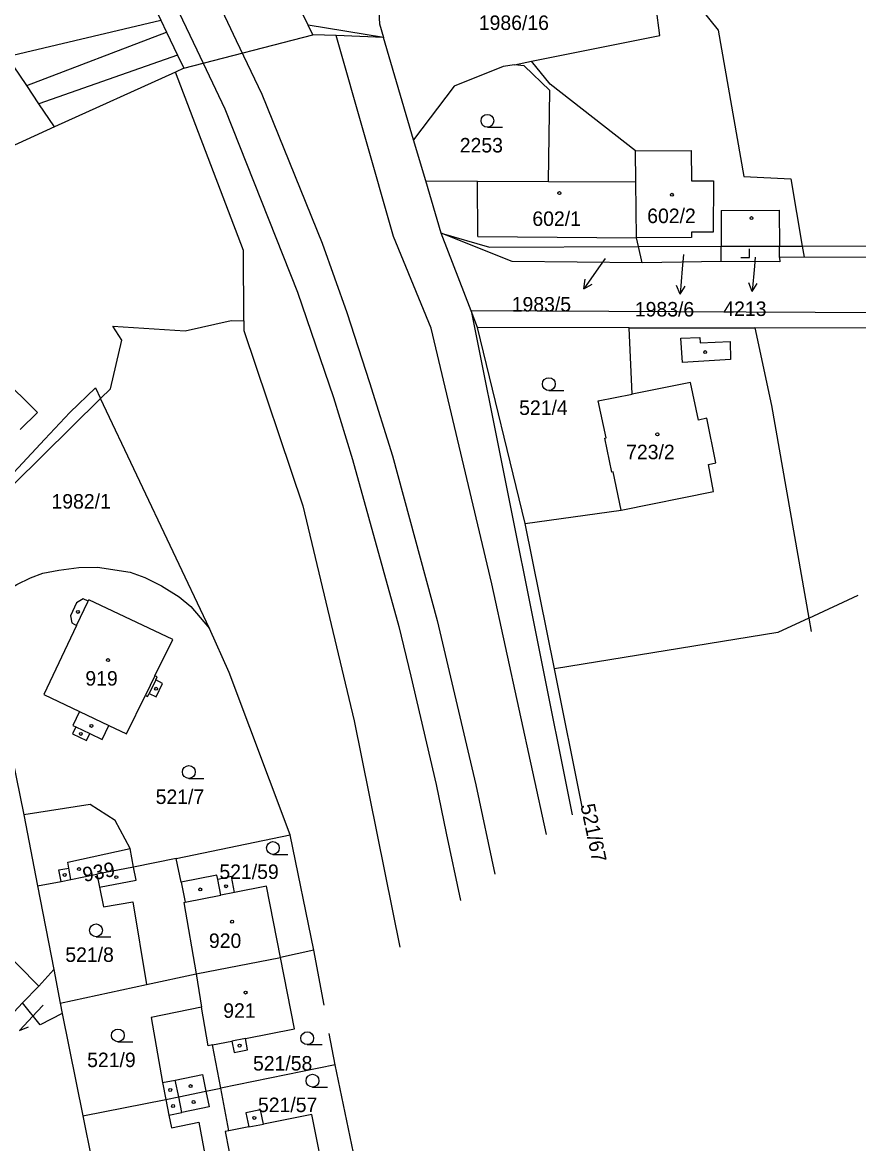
# Model space of a CAD drawing. Extents: x -679220 to -673243, y -1075091 to -1066557.
# Drawn here: x -675840.9 to -675742.9, y -1071652.9 to -1071521.5 of the extents above; entities that cross this region are included whole.
import ezdxf

# ---------------------------------------------------------------- set-up
doc = ezdxf.new("R2010")
doc.units = 0
for name, color, linetype in [('Hranice parcel', 7, 'Continuous'), ('Parcelní čísla', 7, 'Continuous'), ('Pop  PČ popisy', 7, 'Continuous'), ('Poz předměty', 7, 'Continuous'), ('Vnitřní kresba', 7, 'Continuous'), ('Značky budov', 7, 'Continuous'), ('Značky kultur', 7, 'Continuous')]:
    doc.layers.add(name, color=color, linetype=linetype)

msp = doc.modelspace()

# ---------------------------------------------------------------- linework, layer by layer
at = {"layer": 'Hranice parcel'}
for p, q in [((-675762.66, -1071518.33), (-675759.37, -1071522.39)), ((-675798.6, -1071523.24), (-675804.16, -1071523.03)), ((-675795.08, -1071535.25), (-675798.6, -1071523.24)), ((-675783.25, -1071526.44), (-675781.27, -1071526.04)), ((-675779.07, -1071528.74), (-675781.27, -1071526.04)), ((-675822.98, -1071527.31), (-675837.15, -1071533.74)), ((-675769.07, -1071536.52), (-675779.07, -1071528.74)), ((-675793.66, -1071540.05), (-675795.08, -1071535.25)), ((-675791.86, -1071546.18), (-675793.66, -1071540.05)), ((-675750.86, -1071539.81), (-675749.53, -1071547.7)), ((-675788.35, -1071555.28), (-675791.86, -1071546.18)), ((-675783.51, -1071549.52), (-675791.86, -1071546.18)), ((-675768.73, -1071547.76), (-675759.03, -1071547.73)), ((-675768.3, -1071549.66), (-675768.73, -1071547.76)), ((-675759.02, -1071549.52), (-675759.03, -1071547.73)), ((-675749.53, -1071547.7), (-675749.31, -1071549.02)), ((-675768.3, -1071549.66), (-675783.51, -1071549.52)), ((-675759.02, -1071549.52), (-675768.3, -1071549.66)), ((-675719.35, -1071549.05), (-675749.31, -1071549.02)), ((-675718.61, -1071555.66), (-675788.35, -1071555.28)), ((-675787.58, -1071557.26), (-675788.35, -1071555.28)), ((-675769.8, -1071557.28), (-675787.58, -1071557.26)), ((-675781.99, -1071580.21), (-675787.58, -1071557.26)), ((-675769.8, -1071557.28), (-675755.1, -1071557.3)), ((-675718.42, -1071557.34), (-675755.1, -1071557.3)), ((-675818.99, -1071592.52), (-675831.77, -1071565.57)), ((-675778.56, -1071597.27), (-675781.99, -1071580.21)), ((-675845.69, -1071590.25), (-675840.78, -1071614.39)), ((-675775.31, -1071613.45), (-675778.56, -1071597.27)), ((-675840.78, -1071614.39), (-675839.16, -1071622.71)), ((-675822.9, -1071619.49), (-675809.53, -1071616.74)), ((-675806.79, -1071630.23), (-675809.53, -1071616.74)), ((-675822.9, -1071619.49), (-675827.9, -1071620.52)), ((-675827.9, -1071620.52), (-675832.19, -1071621.34)), ((-675839.16, -1071622.71), (-675837.26, -1071632.53)), ((-675848.96, -1071624.39), (-675839.01, -1071634.47)), ((-675820.58, -1071633.03), (-675810.68, -1071631.09)), ((-675806.79, -1071630.23), (-675810.68, -1071631.09)), ((-675805.58, -1071636.68), (-675806.79, -1071630.23)), ((-675839.01, -1071634.47), (-675837.26, -1071632.53)), ((-675837.26, -1071632.53), (-675836.49, -1071636.46)), ((-675826.37, -1071634.28), (-675820.58, -1071633.03)), ((-675840.91, -1071636.43), (-675839.01, -1071634.47)), ((-675836.49, -1071636.46), (-675826.37, -1071634.28)), ((-675840.91, -1071636.43), (-675848.4, -1071644.43)), ((-675836.49, -1071636.46), (-675836.25, -1071637.68)), ((-675836.25, -1071637.68), (-675833.84, -1071649.66)), ((-675804.27, -1071643.7), (-675804.96, -1071640.02)), ((-675804.27, -1071643.7), (-675817.68, -1071646.43)), ((-675801.46, -1071657.17), (-675804.27, -1071643.7)), ((-675833.84, -1071649.66), (-675824.13, -1071647.74)), ((-675833.84, -1071649.66), (-675832.79, -1071654.92))]:
    msp.add_line(p, q, dxfattribs=at)
for points in [[(-675836.69, -1071505.46), (-675832.38, -1071505.2), (-675831.88, -1071506.24), (-675829.96, -1071510.26), (-675824.71, -1071521.21), (-675824.03, -1071522.63), (-675822.74, -1071525.31), (-675822, -1071526.86), (-675822.98, -1071527.31)], [(-675837.15, -1071533.74), (-675838.99, -1071531.01), (-675840.42, -1071528.88), (-675842.72, -1071525.48), (-675850.05, -1071514.58), (-675853.19, -1071509.92), (-675855.42, -1071506.6)], [(-675799.42, -1071515.63), (-675799.23, -1071518.87), (-675799.06, -1071521.66), (-675798.6, -1071523.24)], [(-675804.16, -1071523.03), (-675806.88, -1071522.93), (-675807.43, -1071521.79), (-675808.59, -1071519.4), (-675809.31, -1071517.91)], [(-675781.27, -1071526.04), (-675766.22, -1071523), (-675766.64, -1071519.74), (-675762.66, -1071518.33)], [(-675759.37, -1071522.39), (-675756.39, -1071539.53), (-675750.86, -1071539.81)], [(-675779.51, -1071616.68), (-675785.92, -1071587.32), (-675793.01, -1071557.34), (-675797.45, -1071546.6), (-675804.16, -1071523.03)], [(-675814.99, -1071556.47), (-675815.03, -1071548.22), (-675822.98, -1071527.31)], [(-675783.25, -1071526.44), (-675784.6, -1071526.66), (-675790.31, -1071528.97), (-675795.08, -1071535.25)], [(-675793.66, -1071540.05), (-675787.59, -1071540.08), (-675779.29, -1071540.12), (-675779.13, -1071529.46), (-675782.14, -1071526.56), (-675783.25, -1071526.44)], [(-675837.15, -1071533.74), (-675848.11, -1071538.72), (-675877.36, -1071543.69), (-675912.93, -1071549.73), (-675950.9, -1071556.66), (-675972.74, -1071561.14), (-676014.26, -1071571.02)], [(-675768.73, -1071547.76), (-675768.97, -1071546.72), (-675769.04, -1071540.18), (-675769.07, -1071536.52)], [(-675791.86, -1071546.18), (-675786.19, -1071547.82), (-675768.73, -1071547.76)], [(-675759.03, -1071547.73), (-675752.2, -1071547.71), (-675749.53, -1071547.7)], [(-675749.53, -1071547.7), (-675689.36, -1071547.5)], [(-675749.31, -1071549.02), (-675752.18, -1071549.03), (-675752.17, -1071549.55), (-675759.02, -1071549.52)], [(-675788.35, -1071555.28), (-675776.51, -1071614.37)], [(-675831.77, -1071565.57), (-675830.61, -1071564.43), (-675829.28, -1071558.72), (-675830.34, -1071557.08), (-675821.87, -1071557.66), (-675816.45, -1071556.43), (-675814.99, -1071556.47)], [(-675814.99, -1071556.47), (-675814.98, -1071557.6), (-675808.08, -1071578.16), (-675802.06, -1071603.35), (-675796.71, -1071629.88)], [(-675781.99, -1071580.21), (-675770.74, -1071578.68), (-675771.69, -1071574.18), (-675771.84, -1071574.21), (-675772.68, -1071570.22), (-675772.53, -1071570.19), (-675773.45, -1071565.86), (-675769.47, -1071565.06), (-675769.8, -1071557.28)], [(-675755.1, -1071557.3), (-675753.14, -1071566.4), (-675748.76, -1071591.32)], [(-675845.34, -1071564.8), (-675843.47, -1071562.95), (-675839.16, -1071567.22), (-675841.2, -1071569.22)], [(-675846.21, -1071576.54), (-675845.1, -1071577.61), (-675838.31, -1071570.35), (-675835.37, -1071567.23), (-675832.35, -1071564.34), (-675831.77, -1071565.57)], [(-675831.77, -1071565.57), (-675862.32, -1071595.73), (-675894.88, -1071628.17), (-675911.82, -1071645.32), (-675911.96, -1071645.47)], [(-675845.69, -1071590.25), (-675844.52, -1071589.23), (-675843.28, -1071588.35), (-675841.6, -1071587.37), (-675839.97, -1071586.6), (-675838.55, -1071586.06), (-675836.65, -1071585.68), (-675834.32, -1071585.37), (-675832.14, -1071585.35), (-675828.3, -1071585.95), (-675826.58, -1071586.56), (-675824.62, -1071587.52), (-675822.57, -1071588.81), (-675821.2, -1071589.94), (-675818.99, -1071592.52)], [(-675833.04, -1071604.85), (-675831.58, -1071605.55), (-675830.8, -1071603.9), (-675828.74, -1071604.89), (-675826.52, -1071600.37), (-675826.25, -1071600.5), (-675826.07, -1071600.14), (-675825.26, -1071600.54), (-675824.49, -1071598.97), (-675825.3, -1071598.57), (-675825.12, -1071598.21), (-675825.39, -1071598.08), (-675823.29, -1071593.82), (-675833.15, -1071589.18), (-675833.21, -1071589.32), (-675833.8, -1071589.04), (-675834.57, -1071589.51), (-675835.3, -1071591.04), (-675835.15, -1071591.89), (-675834.57, -1071592.17), (-675838.41, -1071600.27), (-675834.22, -1071602.27), (-675835, -1071603.91), (-675834.66, -1071604.07), (-675835.06, -1071604.89), (-675833.43, -1071605.67), (-675833.04, -1071604.85)], [(-675748.76, -1071591.32), (-675742.96, -1071588.63)], [(-675748.76, -1071591.32), (-675752.38, -1071593), (-675778.56, -1071597.27)], [(-675748.76, -1071591.32), (-675748.49, -1071592.87)], [(-675809.53, -1071616.74), (-675816.7, -1071597.7), (-675818.99, -1071592.52)], [(-675827.9, -1071620.52), (-675828.31, -1071618.32), (-675830.05, -1071615.03), (-675832.98, -1071613.18), (-675840.78, -1071614.39)], [(-675810.68, -1071631.09), (-675812.33, -1071622.75), (-675816.06, -1071623.49), (-675816.43, -1071621.63), (-675818.03, -1071621.95), (-675818.13, -1071621.46), (-675822.32, -1071622.29), (-675822.9, -1071619.49)], [(-675839.16, -1071622.71), (-675836.39, -1071622.18), (-675835.26, -1071621.96), (-675832.19, -1071621.34)], [(-675832.19, -1071621.34), (-675831.88, -1071622.86), (-675831.42, -1071625.17), (-675827.98, -1071624.59), (-675826.37, -1071634.28)], [(-675817.68, -1071646.43), (-675818.66, -1071641.36), (-675816.38, -1071640.91), (-675816.12, -1071642.23), (-675814.53, -1071641.92), (-675814.79, -1071640.6), (-675809.02, -1071639.48), (-675810.68, -1071631.09)], [(-675820.58, -1071633.03), (-675819.92, -1071636.93), (-675825.85, -1071638.16), (-675824.49, -1071645.78), (-675824.13, -1071647.74)], [(-675836.25, -1071637.68), (-675838.84, -1071639), (-675840.91, -1071636.43)], [(-675824.13, -1071647.74), (-675822.61, -1071647.43), (-675819.42, -1071646.78), (-675817.68, -1071646.43)], [(-675805.33, -1071657.94), (-675807.01, -1071649.5), (-675812.69, -1071650.63), (-675813.02, -1071648.97), (-675814.74, -1071649.31), (-675814.41, -1071650.97), (-675816.72, -1071651.43), (-675817.68, -1071646.43)], [(-675824.13, -1071647.74), (-675823.76, -1071649.58), (-675823.45, -1071651.08), (-675820.25, -1071650.4), (-675818.38, -1071660.53)]]:
    msp.add_lwpolyline(points, dxfattribs=at)
at = {"layer": 'Pop  PČ popisy'}
for p, q in [((-675763.44, -1071548.68), (-675763.59, -1071550.36)), ((-675772.64, -1071549.16), (-675773.4, -1071550.25)), ((-675755.04, -1071549.02), (-675755.14, -1071550.05)), ((-675773.4, -1071550.25), (-675775.12, -1071552.71)), ((-675763.59, -1071550.36), (-675763.85, -1071553.35)), ((-675755.14, -1071550.05), (-675755.4, -1071553.04)), ((-675775.12, -1071552.71), (-675774.96, -1071551.6)), ((-675775.12, -1071552.71), (-675774.14, -1071552.18)), ((-675763.85, -1071553.35), (-675764.26, -1071552.31)), ((-675763.85, -1071553.35), (-675763.27, -1071552.4)), ((-675755.4, -1071553.04), (-675755.81, -1071552)), ((-675755.4, -1071553.04), (-675754.82, -1071552.09)), ((-675838.5, -1071636.68), (-675839.21, -1071637.45)), ((-675839.21, -1071637.45), (-675841.26, -1071639.65)), ((-675841.26, -1071639.65), (-675840.21, -1071639.25))]:
    msp.add_line(p, q, dxfattribs=at)
at = {"layer": 'Poz předměty'}
for p, q in [((-675824.81, -1071504.74), (-675815.86, -1071523.61)), ((-675829.46, -1071505.81), (-675820.49, -1071524.71)), ((-675815.86, -1071523.61), (-675812.88, -1071529.89)), ((-675820.49, -1071524.71), (-675817.21, -1071531.6)), ((-675812.88, -1071529.89), (-675805.78, -1071547.38)), ((-675817.21, -1071531.6), (-675808.69, -1071553.12)), ((-675805.78, -1071547.38), (-675802.9, -1071555.49)), ((-675808.69, -1071553.12), (-675804.47, -1071565.45)), ((-675802.9, -1071555.49), (-675800.26, -1071563.7)), ((-675800.26, -1071563.7), (-675797.56, -1071572.28)), ((-675804.47, -1071565.45), (-675802.23, -1071572.72)), ((-675797.56, -1071572.28), (-675792.31, -1071591.6)), ((-675802.23, -1071572.72), (-675796.82, -1071592.32)), ((-675792.31, -1071591.6), (-675787.78, -1071610.85)), ((-675796.82, -1071592.32), (-675795.39, -1071598.12)), ((-675795.39, -1071598.12), (-675792.45, -1071610.82)), ((-675792.45, -1071610.82), (-675791.26, -1071616.55)), ((-675787.78, -1071610.85), (-675785.56, -1071621.32)), ((-675791.26, -1071616.55), (-675789.6, -1071624.42))]:
    msp.add_line(p, q, dxfattribs=at)
at = {"layer": 'Vnitřní kresba'}
for p, q in [((-675842.72, -1071525.48), (-675824.71, -1071521.21)), ((-675798.6, -1071523.24), (-675807.43, -1071521.79)), ((-675840.42, -1071528.88), (-675824.03, -1071522.63)), ((-675822, -1071526.86), (-675806.88, -1071522.93)), ((-675822.74, -1071525.31), (-675838.99, -1071531.01)), ((-675769.07, -1071536.52), (-675762.55, -1071536.51)), ((-675762.55, -1071536.51), (-675762.53, -1071540.04)), ((-675787.54, -1071546.58), (-675787.59, -1071540.08)), ((-675779.29, -1071540.12), (-675769.04, -1071540.18)), ((-675762.53, -1071540.04), (-675759.93, -1071540.05)), ((-675759.93, -1071540.05), (-675759.99, -1071546.06)), ((-675759.05, -1071543.52), (-675752.25, -1071543.5)), ((-675759.05, -1071543.52), (-675759.03, -1071547.73)), ((-675752.25, -1071543.5), (-675752.2, -1071547.71)), ((-675762.51, -1071546.06), (-675762.51, -1071546.68)), ((-675759.99, -1071546.06), (-675762.51, -1071546.06)), ((-675787.54, -1071546.58), (-675768.97, -1071546.72)), ((-675762.51, -1071546.68), (-675768.97, -1071546.72)), ((-675752.18, -1071549.03), (-675752.2, -1071547.71)), ((-675763.76, -1071558.51), (-675761.52, -1071558.43)), ((-675763.55, -1071561.36), (-675763.76, -1071558.51)), ((-675761.52, -1071558.43), (-675761.49, -1071559.03)), ((-675761.49, -1071559.03), (-675757.99, -1071558.91)), ((-675757.99, -1071558.91), (-675757.93, -1071561.02)), ((-675757.93, -1071561.02), (-675763.55, -1071561.36)), ((-675762.61, -1071563.68), (-675769.47, -1071565.06)), ((-675761.68, -1071568.1), (-675762.61, -1071563.68)), ((-675760.71, -1071567.89), (-675761.68, -1071568.1)), ((-675759.64, -1071573.13), (-675760.71, -1071567.89)), ((-675760.53, -1071573.3), (-675759.64, -1071573.13)), ((-675759.95, -1071576.49), (-675760.53, -1071573.3)), ((-675770.74, -1071578.68), (-675759.95, -1071576.49)), ((-675834.57, -1071592.17), (-675833.21, -1071589.32)), ((-675825.39, -1071598.08), (-675826.52, -1071600.37)), ((-675825.3, -1071598.57), (-675826.07, -1071600.14)), ((-675834.22, -1071602.27), (-675830.8, -1071603.9)), ((-675834.66, -1071604.07), (-675833.04, -1071604.85)), ((-675835.62, -1071619.93), (-675828.31, -1071618.32)), ((-675836.65, -1071620.82), (-675835.5, -1071620.62)), ((-675836.39, -1071622.18), (-675836.65, -1071620.82)), ((-675835.5, -1071620.62), (-675835.62, -1071619.93)), ((-675835.26, -1071621.96), (-675835.5, -1071620.62)), ((-675827.6, -1071622.05), (-675827.9, -1071620.52)), ((-675831.88, -1071622.86), (-675827.6, -1071622.05)), ((-675822.32, -1071622.29), (-675821.85, -1071624.63)), ((-675817.67, -1071623.81), (-675818.03, -1071621.95)), ((-675816.06, -1071623.49), (-675817.67, -1071623.81)), ((-675822, -1071624.66), (-675821.85, -1071624.63)), ((-675822, -1071624.66), (-675820.58, -1071633.03)), ((-675821.85, -1071624.63), (-675817.67, -1071623.81)), ((-675819.15, -1071641.45), (-675819.92, -1071636.93)), ((-675814.79, -1071640.6), (-675816.38, -1071640.91)), ((-675818.66, -1071641.36), (-675819.15, -1071641.45)), ((-675824.49, -1071645.78), (-675823.01, -1071645.47)), ((-675823.01, -1071645.47), (-675819.82, -1071644.82)), ((-675822.61, -1071647.43), (-675823.01, -1071645.47)), ((-675819.82, -1071644.82), (-675819.42, -1071646.78)), ((-675819.42, -1071646.78), (-675819.05, -1071648.62)), ((-675822.24, -1071649.27), (-675822.61, -1071647.43)), ((-675823.76, -1071649.58), (-675822.24, -1071649.27)), ((-675819.05, -1071648.62), (-675822.24, -1071649.27)), ((-675814.41, -1071650.97), (-675812.69, -1071650.63)), ((-675816.72, -1071651.43), (-675817.16, -1071651.51)), ((-675817.16, -1071651.51), (-675815.49, -1071659.95))]:
    msp.add_line(p, q, dxfattribs=at)
at = {"layer": 'Značky budov'}
for centre in [(-675778, -1071541.49), (-675764.81, -1071541.69), (-675755.48, -1071544.43), (-675760.91, -1071560.14), (-675766.51, -1071569.78), (-675834.42, -1071590.59), (-675830.89, -1071596.24), (-675825.26, -1071599.6), (-675832.84, -1071603.96), (-675834.08, -1071604.89), (-675834.29, -1071620.74), (-675835.97, -1071621.42), (-675829.92, -1071621.69), (-675820.09, -1071623.13), (-675817.06, -1071622.75), (-675816.35, -1071626.91), (-675814.78, -1071635.22), (-675815.48, -1071641.44), (-675823.6, -1071646.64), (-675821.22, -1071646.18), (-675823.26, -1071648.52), (-675820.87, -1071648.05), (-675813.75, -1071649.91)]:
    msp.add_circle(centre, 0.175, dxfattribs=at)
at = {"layer": 'Značky kultur'}
for p, q in [((-675786.43, -1071533.77), (-675784.68, -1071533.77)), ((-675755.73, -1071549.04), (-675755.73, -1071548.04)), ((-675756.73, -1071549.04), (-675755.73, -1071549.04)), ((-675779.23, -1071564.64), (-675777.48, -1071564.64)), ((-675821.42, -1071610.11), (-675819.67, -1071610.11)), ((-675811.57, -1071619.02), (-675809.82, -1071619.02)), ((-675832.3, -1071628.67), (-675830.55, -1071628.67)), ((-675829.74, -1071640.99), (-675827.99, -1071640.99)), ((-675807.55, -1071641.32), (-675805.8, -1071641.32)), ((-675806.93, -1071646.3), (-675805.18, -1071646.3))]:
    msp.add_line(p, q, dxfattribs=at)
for centre in [(-675786.43, -1071533.02), (-675779.23, -1071563.89), (-675821.42, -1071609.36), (-675811.57, -1071618.27), (-675832.3, -1071627.92), (-675829.74, -1071640.24), (-675807.55, -1071640.57), (-675806.93, -1071645.55)]:
    msp.add_circle(centre, 0.75, dxfattribs=at)

# ---------------------------------------------------------------- texts
at = {"layer": 'Parcelní čísla'}
for s, p in [('1986/16', (-675787.44, -1071522.37)), ('2253', (-675789.67, -1071536.73)), ('602/2', (-675767.7, -1071545.01)), ('602/1', (-675781.16, -1071545.34)), ('1983/5', (-675783.58, -1071555.38)), ('1983/6', (-675769.15, -1071555.96)), ('4213', (-675758.78, -1071555.9)), ('521/4', (-675782.71, -1071567.5)), ('723/2', (-675770.17, -1071572.69)), ('1982/1', (-675837.52, -1071578.48)), ('919', (-675833.55, -1071599.23)), ('521/7', (-675825.31, -1071613.11)), ('521/59', (-675817.84, -1071621.9)), ('920', (-675819.07, -1071629.99)), ('521/8', (-675835.9, -1071631.62)), ('921', (-675817.39, -1071638.18)), ('521/9', (-675833.34, -1071643.96)), ('521/58', (-675813.9, -1071644.36)), ('521/57', (-675813.32, -1071649.23))]:
    msp.add_text(s, height=1.7, dxfattribs=at).set_placement(p)
for s, rotation, p in [('521/67', 282, (-675775.54, -1071613.27)), ('939', 11, (-675833.69, -1071622.26))]:
    msp.add_text(s, height=1.7, rotation=rotation, dxfattribs=at).set_placement(p)

doc.saveas('drawing.dxf')
